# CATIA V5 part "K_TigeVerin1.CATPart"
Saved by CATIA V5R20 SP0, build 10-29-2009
Part number: Tige_verin1
Bounding box of the stored display mesh (mm): x -2.472 to 2.472, y 108.338 to 190.613, z 168.278 to 173.968
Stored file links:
  G:\Khaled_CFAO_2011\ST2M\ST2M_GR1\hgrenier\Khaled\CAD_ThinkMOTION\K_TigeVerin1.CATPart
  C:\Users\Tom\Documents\Cours 2A\CFAO\Projet thinkmotion\Hugo\porte_outil.CATProduct
  G:\Khaled_CFAO_2011\ST2M\ST2M_GR1\hgrenier\Khaled\CAD_ThinkMOTION\K_Squelette.CATPart
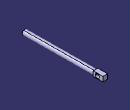
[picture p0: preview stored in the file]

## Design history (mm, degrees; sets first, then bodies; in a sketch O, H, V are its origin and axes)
Parameters
  `diametre_trou_bielle2/verin1` = 4 mm
Set1
  Plane1 "plan_sym": linked copy from another document
  Point1 "Centre_verin/bielle2": linked copy from another document
  Point2 "Centre_bras_verin1": linked copy from another document
Body1 (main body)
  Sketch1 on Plane1, origin (0, 0, 0), H (0, 1, 0), V (0, 0, 1)
    axis line L1 (21.719, 169.887) -> (184.816, 171.511)
    point P1 (21.719, 169.887)
    point P2 (184.816, 171.511)
    reference projected point E1 (184.816, 171.511) from Point1
    reference projected point E2 (21.719, 169.887) from Point2
    line L2 (180.5653, 173.9416) -> (108.338, 173.2224)
    line L3 (108.338, 173.2224) -> (108.3626, 170.7497)
    line L4 (108.3626, 170.7497) -> (180.59, 171.4689)
    line L5 (180.59, 171.4689) -> (180.5653, 173.9416)
    point P5 (108.3626, 170.7497)
    coincidence: P2 E1, P1 E2, P5 L1
    parallelism: L2 L1, L5 L3, L2 L4
    perpendicularity: L2 L3
  Shaft1: profile Sketch1, axis Sketch1.L1, angle 360
  Sketch2 on face of Shaft1 from Sketch1.L5, origin (0, 182.2792, 1.815), H (-1, 0, 0), V (0, -0.01, 1)
    line L1 (-2.4, 172.0623) -> (2.4, 172.0623)
    line L2 (2.4, 172.0623) -> (2.4, 167.2623)
    line L3 (2.4, 167.2623) -> (-2.4, 167.2623)
    line L4 (-2.4, 167.2623) -> (-2.4, 172.0623)
    reference projected point E1 (0, 169.6623) from Point2
    reference projected point E2 (0, 169.6623) from Point2
    reference projected point E3 (0, 169.6623) from Point2
    reference projected point E4 (0, 169.6623) from Point2
    distance E1 L2 = 2.4
    distance E2 L1 = 2.4
    distance E3 L4 = 2.4
    distance E4 L3 = 2.4
    horizontal: L1 H, L3 H
    vertical: L2 V, L4 V
  Pad1: profile Sketch2, direction (0, 1, 0.01), length 10
  Sketch3 on face of Pad1 from Sketch2.L4, origin (2.4, 0, 0), H (0, 1, 0), V (0, 0, 1)
    circle A1 centre (184.816, 171.511) radius 2
    point P1 (184.816, 171.511)
    reference projected point E1 (184.816, 171.511) from Point1
    radius A1 = 2 {= `diametre_trou_bielle2/verin1` /2}
    coincidence: P1 E1
  Pocket1: profile Sketch3, direction (-1, 0, 0), length 10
